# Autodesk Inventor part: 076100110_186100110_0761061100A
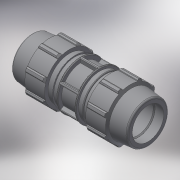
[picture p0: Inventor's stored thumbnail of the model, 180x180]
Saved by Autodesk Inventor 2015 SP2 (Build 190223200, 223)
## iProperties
Created: 2017-02
Part Number: 076100110_186100110_0761061100A
Material: Generic
Description: PLASSON REPAIR COUPLER 110
Document SubType Name: Modeling
Designer: KIM
Mass: 3993.49 g
Surface Area: 4078.17 cm^2
Volume: 3993.49 cm^3
Density: 1 g/cm^3
Appearance: Default
Author: KIM
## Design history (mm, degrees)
derived "07610.ipt"
feature "Solid1::07610.ipt"
tag "TaggingFeature1"
body "Solid1"
other parameters: "d1" = 393, "d4" = 32.75, "d5" = 56.14286, "d7" = 181, "d8" = 135.75, "d9" = 56.14286, "d11" = 3.48571, "d12" = 144.8, "d13" = 120 deg, "d14" = 154, "d15" = 6 deg, "d16" = 162.9, "d18" = 5.5, "d19" = 35 deg, "d20" = 17.5 deg, "d21" = 168.33, "d23" = 0, "d25" = 360 deg, "d27" = 3.62, "d33" = 2.2, "d34" = 9.05, "d36" = 0, "d37" = 2.2, "d38" = 2.2, "d40" = 360 deg, "d42" = 70.74, "d43" = 5.43, "d46" = 3.3, "d50" = 16.22286, "d51" = 144.8, "E_" = 181, "H_" = 393, "l_" = 197, "d49" = 35.93143
